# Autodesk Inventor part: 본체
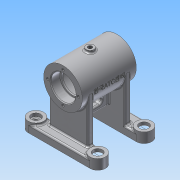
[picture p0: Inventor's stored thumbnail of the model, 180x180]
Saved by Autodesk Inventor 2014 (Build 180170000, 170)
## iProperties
Created: 2015-11
Part Number: 본체
Material: 알루미늄 6061
Document SubType Name: Modeling
Designer: 103-08
Density: 2.71 g/cm^3
Appearance: 알루미늄 - 평지
Mass: 358.948 g
Surface Area: 460.354 cm^2
Volume: 132.453 cm^3
Author: 103-08
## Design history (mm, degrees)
sketch "스케치1"
  geometry: L1 (-40, 40)-(40, 40); L2 (40, 20)-(-40, 20); L3 (-40, -20)-(40, -20); L4 (0, 20)-(0, -8.942); L5 (-40, -40)-(40, -40); A1 r 10 centre (-40, 30) between (-40, 40) and (-40, 20); A2 r 10 centre (40, 30) between (40, 40) and (40, 20); A3 r 10 centre (-40, -30) between (-40, -20) and (-40, -40); A4 r 10 centre (40, -30) between (40, -20) and (40, -40); 1 further point
  constraints: 10 end point, 8 point on circle, 5 tangent, 4 centre point, 3 equal radius, 3 vertical alignment, 2 horizontal alignment, 1 midpoint, 1 parallel, 1 perpendicular
  dimensions: "d2" = 20 diameter of A1; "d3" = 80 distance of A2.centre A1.centre; "d6" = 80 distance of L1.start L1.end; "d7" = 80 distance of L5.start L5.end; "d28" = 40 distance from line of point (0, 0) L1; "d29" = 40 distance from line of point (0, 0) L5
extrude "돌출1" new body sketch "스케치1" distance "d8" = 10; taper "d9" = 0 deg
sketch "스케치4"
  geometry: L1 (-35, 68)-(35, 68); L2 (-35, 84)-(-35, 93); L3 (-35, 93)-(35, 93); L4 (35, 93)-(35, 84); L5 (35, 84)-(23, 84); L6 (23, 84)-(23, 82); L7 (23, 82)-(21, 82); L8 (21, 82)-(21, 89); L9 (21, 89)-(-21, 89); L10 (-21, 89)-(-21, 82); L11 (-21, 82)-(-23, 82); L12 (-23, 82)-(-23, 84); L13 (-23, 84)-(-35, 84); 2 further points
  constraints: 26 end point, 10 parallel, 4 collinear, 2 perpendicular, 2 point on line, 1 horizontal, 1 midpoint, 1 vertical alignment
  dimensions: "d17" = 68 vertical distance of point (0, 0) L1.end; "d18" = 70 distance of L1.start L1.end; "d19" = 12 distance of L12.end L2.start; "d20" = 2 distance of L10.end L11.end; "d21" = 32 diameter of L13 L1; "d22" = 50 diameter of L3 L1; "d23" = 42 diameter of L9 L1; "d24" = 28 diameter of L11 L1
revolve "회전1" sketch "스케치4" stored, may be unused: angle "d25" = 90 deg
sketch "스케치7"
  geometry: L1 (80, -10)-(0, -10) reference; L2 (65, -68)-(65, -10); L3 (15, -68)-(15, -10); A1 r 25 centre (40, -68) between (65, -68) and (15, -68) reference; 1 further point
  constraints: 4 end point, 2 perpendicular, 2 point on circle, 2 point on line, 2 tangent
extrude "돌출2" join sketch "스케치7" distance "d30" = 8; taper "d31" = 0 deg
node "작업 평면2"
sketch "스케치8"
  geometry: C1 r 5 at (0, 0); 1 further point
  constraints: 1 centre point, 1 coincident
  dimensions: "d33" = 10 diameter of C1
extrude "돌출3" join sketch "스케치8" stored distance "d34" = 8; taper "d35" = 0 deg
sketch "스케치9"
  geometry: L1 (0, 0)-(0, 33.311); L2 (0, 0)-(-12.5, 21.651); C1 r 16 at (0, 0) reference; 1 further point
  constraints: 4 end point, 1 vertical, 2 other
  dimensions: "d36" = 30 deg angle of L1 L2
node "작업 평면4"
  node "작업 평면3"
sketch "스케치11"
  geometry: C1 r 6 at (35, 0); 2 further points
  constraints: 1 centre point, 1 horizontal alignment, 1 vertical alignment
  dimensions: "d38" = 12 diameter of C1
extrude "돌출4" join sketch "스케치11" stored distance "d39" = 8; taper "d40" = 0 deg
node "작업 평면6"
sketch "스케치12"
  geometry: L1 (-20, 68)-(-20, 10) reference; L2 (20, 68)-(20, 10) reference; L3 (-20, 23)-(20, 23); L4 (-35, 43)-(35, 43) reference; L5 (-20, 23)-(-20, 43); L6 (20, 43)-(20, 23); L7 (-20, 43)-(-20, 44.75); L8 (20, 44.75)-(20, 43); L9 (20, 44.75)-(-20, 44.75); 1 further point
  constraints: 12 end point, 8 point on line, 2 collinear, 2 perpendicular
  dimensions: "d42" = 20 distance between parallel lines of L3 L4; "d45" = 1.75028 distance between parallel lines of L9 L4
extrude "돌출5" join sketch "스케치12" stored distance "d43" = 8; taper "d44" = 0 deg
sketch "스케치13"
  geometry: L1 (43.322, -20)-(23, -20) reference; L2 (29.5, -8)-(29.5, 8); L3 (36.5, 8)-(36.5, -8); L4 (0, 20)-(10, 20) reference; L5 (0, -20)-(10, -20) reference; L6 (96, 5)-(96, -5) reference; L7 (96, 0)-(10, 0); A1 r 3.5 centre (33, 8) between (36.5, 8) and (29.5, 8); A2 r 3.5 centre (33, -8) between (29.5, -8) and (36.5, -8); 1 further point
  constraints: 6 end point, 4 point on circle, 4 tangent, 2 centre point, 2 perpendicular, 1 equal radius, 1 midpoint
  dimensions: "d48" = 3.5 radius of A2; "d49" = 33 horizontal distance of A2.centre point (0, 0); "d50" = 11.5 dimension on A1 L7; "d51" = 11.5 dimension on A2 L7
extrude "돌출6" cut sketch "스케치13" stored distance "d52" = 8; taper "d53" = 0 deg
node "작업 평면7"
sketch "스케치14"
  geometry: L1 (-5, 28)-(5, 28) reference; L2 (-35, -25)-(-35, 25) reference; L3 (-35, 25)-(35, 25) reference; 2 further points
  constraints: 1 other
  dimensions: "d54" = 35 distance from line of point (0, 0) L2; "d104" = 25 distance from line of L3 point (0, 0)
feature "엠보싱1" sketch "스케치14" dims "d17" = 68, "d18" = 70, "d19" = 12, "d20" = 2, "d21" = 32, "d22" = 50, "d23" = 42, "d24" = 28, "d56" = 0.5, "d57" = 0
sketch "스케치15"
  geometry: C1 r 16 at (0, 0) reference; C2 r 25 at (0, 0) reference; A1 r 20 centre (0, 0) between (0, 20) and (-20, 0); 3 further points
  constraints: 4 point on circle, 2 horizontal alignment, 2 vertical alignment, 1 centre point, 1 coincident
  dimensions: "d58" = 40 diameter of A1
hole "구멍1" sketch "스케치15" at (0, 20), (-20, 0), (20, 0), (0, -20) diameter "d59" = 3.242; stored, may be unused: countersink angle "d63" = 90 deg, drill point angle "d65" = 118 deg; dims "d60" = 8, "d61" = 4, "d62" = 2, "d64" = 10
sketch "스케치16"
  geometry: L1 (40, 40)-(-40, 40) reference; C1 r 10 at (-40, 30); C2 r 10 at (40, 30); A1 r 10 centre (40, 30) between (40, 20) and (40, 40) reference; A2 r 10 centre (-40, 30) between (-40, 40) and (-40, 20) reference; 1 further point
  constraints: 2 centre point, 2 coincident, 1 tangent
  dimensions: "d66" = 20 diameter of C1
extrude "돌출7" join sketch "스케치16" distance "d67" = 3; taper "d68" = 0 deg
hole "구멍2" diameter "d71" = 6; stored, may be unused: countersink angle "d75" = 90 deg, drill point angle "d77" = 0 deg; dims "d69" = 10, "d70" = 10, "d72" = 8, "d73" = 12, "d74" = 4, "d76" = 10
fillet "모깎기1" dims "d78" = 0.3, "d79" = 3
fillet "모깎기2" dims "d80" = 2
fillet "모깎기3" dims "d81" = 2
hole "구멍3" diameter "d84" = 5.188; stored, may be unused: countersink angle "d88" = 90 deg, drill point angle "d90" = 0 deg; dims "d82" = 10, "d83" = 10, "d85" = 8, "d86" = 12, "d87" = 4, "d89" = 10
hole "구멍4" diameter "d93" = 5.188; stored, may be unused: countersink angle "d97" = 90 deg, drill point angle "d99" = 0 deg; dims "d91" = 10, "d92" = 10, "d94" = 8, "d95" = 12, "d96" = 4, "d98" = 10
chamfer "모따기1" distance "d100" = 1; stored, may be unused: second distance "d101" = 2, angle "d102" = 45 deg
fillet "모깎기4" dims "d103" = 2
chamfer "모따기2" distance "d105" = 1; stored, may be unused: second distance "d106" = 2, angle "d107" = 45 deg
node "솔리드1"
mirror "대칭1"
mirror "대칭2"
mirror "대칭3"
mirror "대칭4"
other parameters: "d32" = 96, "d37" = 3, "d41" = 0
